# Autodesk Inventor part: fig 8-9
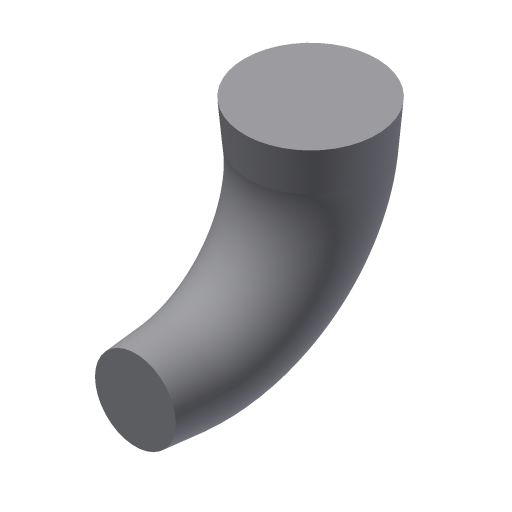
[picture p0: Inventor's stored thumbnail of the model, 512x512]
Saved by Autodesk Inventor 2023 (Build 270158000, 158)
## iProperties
Created: 2001-12
Part Number: fig 8-9
Document SubType Name: Modeling
Designer: CADSoft
Density: 1 g/cm^3
Material: Generic
Appearance: Default
Control State: 0
Master: False
Checked Out: False
Shininess: 77.0
Length Units: 11269
Angle Units: 11279
Time Units: 11290
Mass Units: 11283
Length Display Precision: 3
Angle Display Precision: 2
Density: 0.0
Volumn: 0.0
Area: 0.0
PropertySet Name: Model Information
Author: CADSoft
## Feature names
1. Sweep7
## Parameters: d4 = 15 mm, d5 = 15 mm, d13 = 5 deg, d14 = 0
